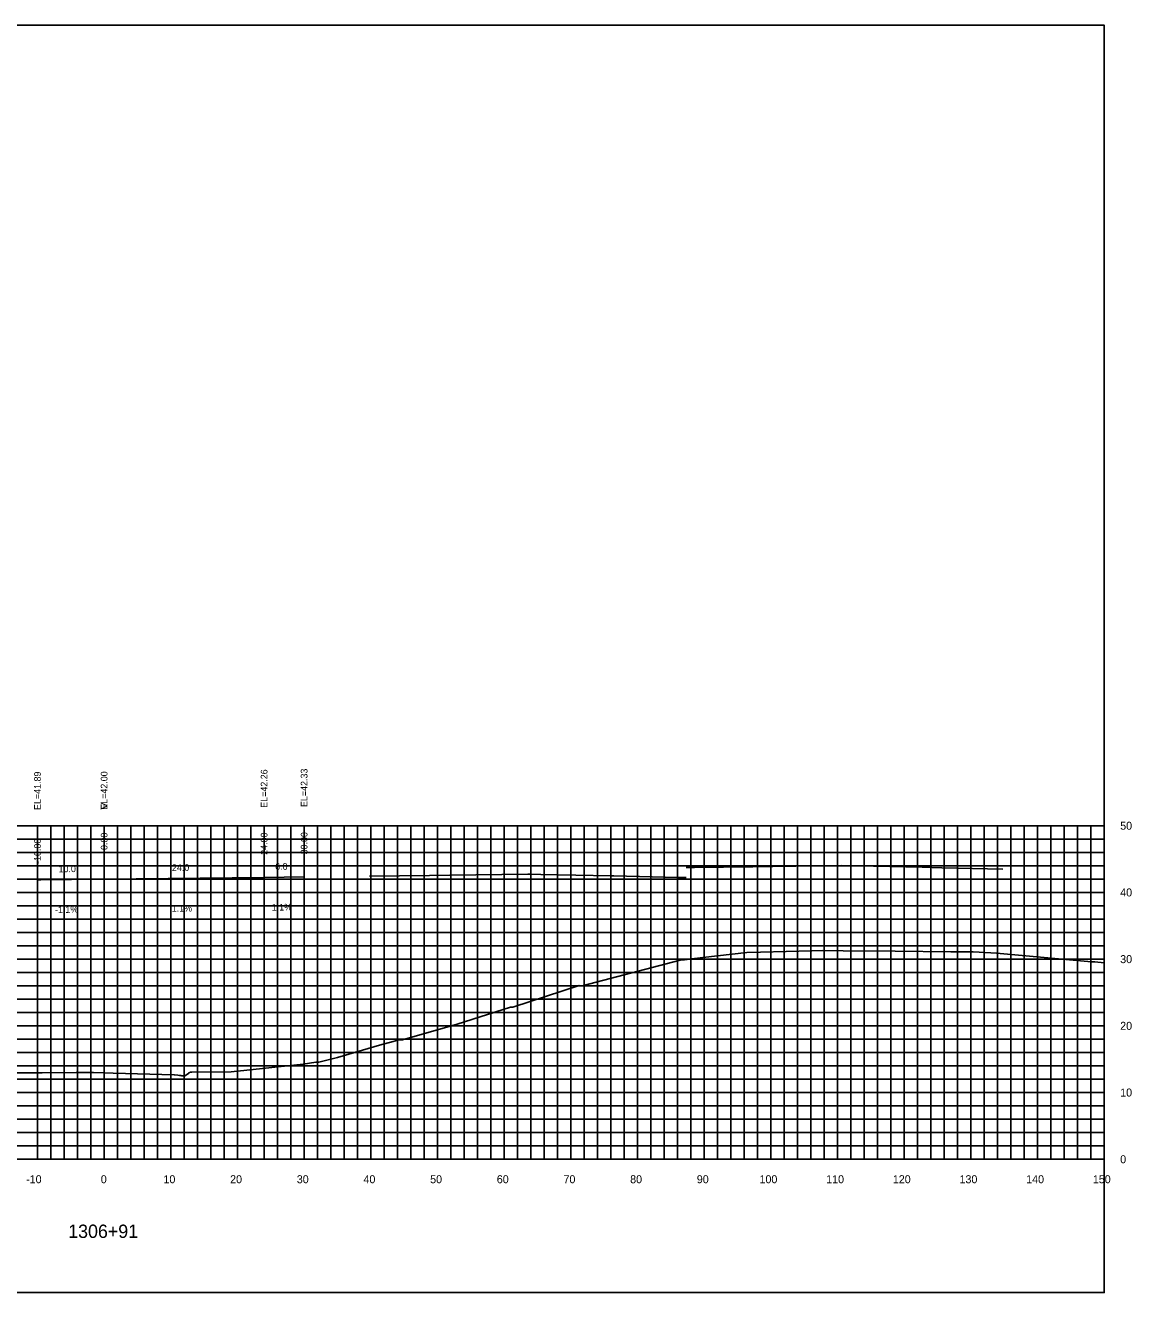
# Model space of a CAD drawing. Extents: x 1797714 to 1804825, y 249015 to 250269.
# Drawn here: x 1804632.3 to 1804798.3, y 249628.2 to 249818.2 of the extents above; entities that cross this region are included whole.
import ezdxf

# ---------------------------------------------------------------- set-up
doc = ezdxf.new("R2010")
doc.units = 0
for name, color, linetype in [('1', 7, 'Continuous'), ('10', 7, 'Continuous'), ('3', 7, 'Continuous'), ('31', 7, 'Continuous'), ('4', 7, 'Continuous'), ('60', 7, 'Continuous'), ('CL-CNST', 7, 'Continuous'), ('Level 62', 7, 'Continuous'), ('M-ROADS', 7, 'Continuous'), ('WEARING', 7, 'Continuous')]:
    doc.layers.add(name, color=color, linetype=linetype)

msp = doc.modelspace()

# ---------------------------------------------------------------- linework, layer by layer
for p, q in [((1804668.16, 249690.43), (1804668.16, 249692.43)), ((1804668.16, 249690.43), (1804668.16, 249692.43)), ((1804674.16, 249690.5), (1804674.16, 249692.5)), ((1804634.16, 249690.06), (1804634.16, 249692.06)), ((1804644.16, 249690.17), (1804644.16, 249692.17))]:
    msp.add_line(p, q)
msp.add_lwpolyline([(1804494.16, 249628.17), (1804794.16, 249628.17), (1804794.16, 249818.17), (1804494.16, 249818.17)], close=True)
at = {"layer": '60'}
for p, q in [((1804794.16, 249648.17), (1804794.16, 249698.17)), ((1804794.22, 249698.17), (1804794.16, 249698.17)), ((1804794.22, 249688.17), (1804794.16, 249688.17)), ((1804794.22, 249678.17), (1804794.16, 249678.17)), ((1804794.22, 249668.17), (1804794.16, 249668.17)), ((1804794.22, 249658.17), (1804794.16, 249658.17)), ((1804494.16, 249648.17), (1804794.16, 249648.17)), ((1804634.16, 249648.11), (1804634.16, 249648.17)), ((1804644.16, 249648.11), (1804644.16, 249648.17)), ((1804654.16, 249648.11), (1804654.16, 249648.17)), ((1804664.16, 249648.11), (1804664.16, 249648.17)), ((1804674.16, 249648.11), (1804674.16, 249648.17)), ((1804684.16, 249648.11), (1804684.16, 249648.17)), ((1804694.16, 249648.11), (1804694.16, 249648.17)), ((1804704.16, 249648.11), (1804704.16, 249648.17)), ((1804714.16, 249648.11), (1804714.16, 249648.17)), ((1804724.16, 249648.11), (1804724.16, 249648.17)), ((1804734.16, 249648.11), (1804734.16, 249648.17)), ((1804744.16, 249648.11), (1804744.16, 249648.17)), ((1804754.16, 249648.11), (1804754.16, 249648.17)), ((1804764.16, 249648.11), (1804764.16, 249648.17)), ((1804774.16, 249648.11), (1804774.16, 249648.17)), ((1804784.16, 249648.11), (1804784.16, 249648.17)), ((1804794.16, 249648.11), (1804794.16, 249648.17)), ((1804794.22, 249648.17), (1804794.16, 249648.17))]:
    msp.add_line(p, q, dxfattribs=at)
at = {"layer": 'CL-CNST'}
for points in [[(1804634.16, 249690.06), (1804644.16, 249690.17), (1804668.16, 249690.43), (1804668.16, 249690.43), (1804674.16, 249690.5)], [(1804683.96, 249690.6), (1804692.96, 249690.72), (1804696.02, 249690.75), (1804707.73, 249690.9), (1804708.09, 249690.9), (1804709.65, 249690.87), (1804720.15, 249690.65), (1804720.59, 249690.64), (1804730.2, 249690.43), (1804730.3, 249690.43), (1804731.45, 249690.4)], [(1804634.16, 249690.07), (1804634.66, 249690.07), (1804643.92, 249690.16), (1804643.94, 249690.16)]]:
    msp.add_lwpolyline(points, dxfattribs=at)
at = {"layer": 'Level 62'}
for p, q in [((1804494.16, 249698.17), (1804794.16, 249698.17)), ((1804494.16, 249698.17), (1804794.16, 249698.17)), ((1804634.16, 249648.17), (1804634.16, 249698.17)), ((1804634.16, 249648.17), (1804634.16, 249698.17)), ((1804636.16, 249648.17), (1804636.16, 249698.17)), ((1804636.16, 249648.17), (1804636.16, 249698.17)), ((1804638.16, 249648.17), (1804638.16, 249698.17)), ((1804638.16, 249648.17), (1804638.16, 249698.17)), ((1804640.16, 249648.17), (1804640.16, 249698.17)), ((1804640.16, 249648.17), (1804640.16, 249698.17)), ((1804642.16, 249648.17), (1804642.16, 249698.17)), ((1804642.16, 249648.17), (1804642.16, 249698.17)), ((1804644.16, 249648.17), (1804644.16, 249698.17)), ((1804644.16, 249648.17), (1804644.16, 249698.17)), ((1804646.16, 249648.17), (1804646.16, 249698.17)), ((1804646.16, 249648.17), (1804646.16, 249698.17)), ((1804648.16, 249648.17), (1804648.16, 249698.17)), ((1804648.16, 249648.17), (1804648.16, 249698.17)), ((1804650.16, 249648.17), (1804650.16, 249698.17)), ((1804650.16, 249648.17), (1804650.16, 249698.17)), ((1804652.16, 249648.17), (1804652.16, 249698.17)), ((1804652.16, 249648.17), (1804652.16, 249698.17)), ((1804654.16, 249648.17), (1804654.16, 249698.17)), ((1804654.16, 249648.17), (1804654.16, 249698.17)), ((1804656.16, 249648.17), (1804656.16, 249698.17)), ((1804656.16, 249648.17), (1804656.16, 249698.17)), ((1804658.16, 249648.17), (1804658.16, 249698.17)), ((1804658.16, 249648.17), (1804658.16, 249698.17)), ((1804660.16, 249648.17), (1804660.16, 249698.17)), ((1804660.16, 249648.17), (1804660.16, 249698.17)), ((1804662.16, 249648.17), (1804662.16, 249698.17)), ((1804662.16, 249648.17), (1804662.16, 249698.17)), ((1804664.16, 249648.17), (1804664.16, 249698.17)), ((1804664.16, 249648.17), (1804664.16, 249698.17)), ((1804666.16, 249648.17), (1804666.16, 249698.17)), ((1804666.16, 249648.17), (1804666.16, 249698.17)), ((1804668.16, 249648.17), (1804668.16, 249698.17)), ((1804668.16, 249648.17), (1804668.16, 249698.17)), ((1804670.16, 249648.17), (1804670.16, 249698.17)), ((1804670.16, 249648.17), (1804670.16, 249698.17)), ((1804672.16, 249648.17), (1804672.16, 249698.17)), ((1804672.16, 249648.17), (1804672.16, 249698.17)), ((1804674.16, 249648.17), (1804674.16, 249698.17)), ((1804674.16, 249648.17), (1804674.16, 249698.17)), ((1804676.16, 249648.17), (1804676.16, 249698.17)), ((1804676.16, 249648.17), (1804676.16, 249698.17)), ((1804678.16, 249648.17), (1804678.16, 249698.17)), ((1804678.16, 249648.17), (1804678.16, 249698.17)), ((1804680.16, 249648.17), (1804680.16, 249698.17)), ((1804680.16, 249648.17), (1804680.16, 249698.17)), ((1804682.16, 249648.17), (1804682.16, 249698.17)), ((1804682.16, 249648.17), (1804682.16, 249698.17)), ((1804684.16, 249648.17), (1804684.16, 249698.17)), ((1804684.16, 249648.17), (1804684.16, 249698.17)), ((1804686.16, 249648.17), (1804686.16, 249698.17)), ((1804686.16, 249648.17), (1804686.16, 249698.17)), ((1804688.16, 249648.17), (1804688.16, 249698.17)), ((1804688.16, 249648.17), (1804688.16, 249698.17)), ((1804690.16, 249648.17), (1804690.16, 249698.17)), ((1804690.16, 249648.17), (1804690.16, 249698.17)), ((1804692.16, 249648.17), (1804692.16, 249698.17)), ((1804692.16, 249648.17), (1804692.16, 249698.17)), ((1804694.16, 249648.17), (1804694.16, 249698.17)), ((1804694.16, 249648.17), (1804694.16, 249698.17)), ((1804696.16, 249648.17), (1804696.16, 249698.17)), ((1804696.16, 249648.17), (1804696.16, 249698.17)), ((1804698.16, 249648.17), (1804698.16, 249698.17)), ((1804698.16, 249648.17), (1804698.16, 249698.17)), ((1804700.16, 249648.17), (1804700.16, 249698.17)), ((1804700.16, 249648.17), (1804700.16, 249698.17)), ((1804702.16, 249648.17), (1804702.16, 249698.17)), ((1804702.16, 249648.17), (1804702.16, 249698.17)), ((1804704.16, 249648.17), (1804704.16, 249698.17)), ((1804704.16, 249648.17), (1804704.16, 249698.17)), ((1804706.16, 249648.17), (1804706.16, 249698.17)), ((1804706.16, 249648.17), (1804706.16, 249698.17)), ((1804708.16, 249648.17), (1804708.16, 249698.17)), ((1804708.16, 249648.17), (1804708.16, 249698.17)), ((1804710.16, 249648.17), (1804710.16, 249698.17)), ((1804710.16, 249648.17), (1804710.16, 249698.17)), ((1804712.16, 249648.17), (1804712.16, 249698.17)), ((1804712.16, 249648.17), (1804712.16, 249698.17)), ((1804714.16, 249648.17), (1804714.16, 249698.17)), ((1804714.16, 249648.17), (1804714.16, 249698.17)), ((1804716.16, 249648.17), (1804716.16, 249698.17)), ((1804716.16, 249648.17), (1804716.16, 249698.17)), ((1804718.16, 249648.17), (1804718.16, 249698.17)), ((1804718.16, 249648.17), (1804718.16, 249698.17)), ((1804720.16, 249648.17), (1804720.16, 249698.17)), ((1804720.16, 249648.17), (1804720.16, 249698.17)), ((1804722.16, 249648.17), (1804722.16, 249698.17)), ((1804722.16, 249648.17), (1804722.16, 249698.17)), ((1804724.16, 249648.17), (1804724.16, 249698.17)), ((1804724.16, 249648.17), (1804724.16, 249698.17)), ((1804726.16, 249648.17), (1804726.16, 249698.17)), ((1804726.16, 249648.17), (1804726.16, 249698.17)), ((1804728.16, 249648.17), (1804728.16, 249698.17)), ((1804728.16, 249648.17), (1804728.16, 249698.17)), ((1804730.16, 249648.17), (1804730.16, 249698.17)), ((1804730.16, 249648.17), (1804730.16, 249698.17)), ((1804732.16, 249648.17), (1804732.16, 249698.17)), ((1804732.16, 249648.17), (1804732.16, 249698.17)), ((1804734.16, 249648.17), (1804734.16, 249698.17)), ((1804734.16, 249648.17), (1804734.16, 249698.17)), ((1804736.16, 249648.17), (1804736.16, 249698.17)), ((1804736.16, 249648.17), (1804736.16, 249698.17)), ((1804738.16, 249648.17), (1804738.16, 249698.17)), ((1804738.16, 249648.17), (1804738.16, 249698.17)), ((1804740.16, 249648.17), (1804740.16, 249698.17)), ((1804740.16, 249648.17), (1804740.16, 249698.17)), ((1804742.16, 249648.17), (1804742.16, 249698.17)), ((1804742.16, 249648.17), (1804742.16, 249698.17)), ((1804744.16, 249648.17), (1804744.16, 249698.17)), ((1804744.16, 249648.17), (1804744.16, 249698.17)), ((1804746.16, 249648.17), (1804746.16, 249698.17)), ((1804746.16, 249648.17), (1804746.16, 249698.17)), ((1804748.16, 249648.17), (1804748.16, 249698.17)), ((1804748.16, 249648.17), (1804748.16, 249698.17)), ((1804750.16, 249648.17), (1804750.16, 249698.17)), ((1804750.16, 249648.17), (1804750.16, 249698.17)), ((1804752.16, 249648.17), (1804752.16, 249698.17)), ((1804752.16, 249648.17), (1804752.16, 249698.17)), ((1804754.16, 249648.17), (1804754.16, 249698.17)), ((1804754.16, 249648.17), (1804754.16, 249698.17)), ((1804756.16, 249648.17), (1804756.16, 249698.17)), ((1804756.16, 249648.17), (1804756.16, 249698.17)), ((1804758.16, 249648.17), (1804758.16, 249698.17)), ((1804758.16, 249648.17), (1804758.16, 249698.17)), ((1804760.16, 249648.17), (1804760.16, 249698.17)), ((1804760.16, 249648.17), (1804760.16, 249698.17)), ((1804762.16, 249648.17), (1804762.16, 249698.17)), ((1804762.16, 249648.17), (1804762.16, 249698.17)), ((1804764.16, 249648.17), (1804764.16, 249698.17)), ((1804764.16, 249648.17), (1804764.16, 249698.17)), ((1804766.16, 249648.17), (1804766.16, 249698.17)), ((1804766.16, 249648.17), (1804766.16, 249698.17)), ((1804768.16, 249648.17), (1804768.16, 249698.17)), ((1804768.16, 249648.17), (1804768.16, 249698.17)), ((1804770.16, 249648.17), (1804770.16, 249698.17)), ((1804770.16, 249648.17), (1804770.16, 249698.17)), ((1804772.16, 249648.17), (1804772.16, 249698.17)), ((1804772.16, 249648.17), (1804772.16, 249698.17)), ((1804774.16, 249648.17), (1804774.16, 249698.17)), ((1804774.16, 249648.17), (1804774.16, 249698.17)), ((1804776.16, 249648.17), (1804776.16, 249698.17)), ((1804776.16, 249648.17), (1804776.16, 249698.17)), ((1804778.16, 249648.17), (1804778.16, 249698.17)), ((1804778.16, 249648.17), (1804778.16, 249698.17)), ((1804780.16, 249648.17), (1804780.16, 249698.17)), ((1804780.16, 249648.17), (1804780.16, 249698.17)), ((1804782.16, 249648.17), (1804782.16, 249698.17)), ((1804782.16, 249648.17), (1804782.16, 249698.17)), ((1804784.16, 249648.17), (1804784.16, 249698.17)), ((1804784.16, 249648.17), (1804784.16, 249698.17)), ((1804786.16, 249648.17), (1804786.16, 249698.17)), ((1804786.16, 249648.17), (1804786.16, 249698.17)), ((1804788.16, 249648.17), (1804788.16, 249698.17)), ((1804788.16, 249648.17), (1804788.16, 249698.17)), ((1804790.16, 249648.17), (1804790.16, 249698.17)), ((1804790.16, 249648.17), (1804790.16, 249698.17)), ((1804792.16, 249648.17), (1804792.16, 249698.17)), ((1804792.16, 249648.17), (1804792.16, 249698.17)), ((1804794.16, 249648.17), (1804794.16, 249698.17)), ((1804794.16, 249648.17), (1804794.16, 249698.17)), ((1804494.16, 249696.17), (1804794.16, 249696.17)), ((1804494.16, 249696.17), (1804794.16, 249696.17)), ((1804494.16, 249694.17), (1804794.16, 249694.17)), ((1804494.16, 249694.17), (1804794.16, 249694.17)), ((1804494.16, 249692.17), (1804794.16, 249692.17)), ((1804494.16, 249692.17), (1804794.16, 249692.17)), ((1804494.16, 249690.17), (1804794.16, 249690.17)), ((1804494.16, 249690.17), (1804794.16, 249690.17)), ((1804494.16, 249688.17), (1804794.16, 249688.17)), ((1804494.16, 249688.17), (1804794.16, 249688.17)), ((1804494.16, 249686.17), (1804794.16, 249686.17)), ((1804494.16, 249686.17), (1804794.16, 249686.17)), ((1804494.16, 249684.17), (1804794.16, 249684.17)), ((1804494.16, 249684.17), (1804794.16, 249684.17)), ((1804494.16, 249682.17), (1804794.16, 249682.17)), ((1804494.16, 249682.17), (1804794.16, 249682.17)), ((1804494.16, 249680.17), (1804794.16, 249680.17)), ((1804494.16, 249680.17), (1804794.16, 249680.17)), ((1804494.16, 249678.17), (1804794.16, 249678.17)), ((1804494.16, 249678.17), (1804794.16, 249678.17)), ((1804494.16, 249676.17), (1804794.16, 249676.17)), ((1804494.16, 249676.17), (1804794.16, 249676.17)), ((1804494.16, 249674.17), (1804794.16, 249674.17)), ((1804494.16, 249674.17), (1804794.16, 249674.17)), ((1804494.16, 249672.17), (1804794.16, 249672.17)), ((1804494.16, 249672.17), (1804794.16, 249672.17)), ((1804494.16, 249670.17), (1804794.16, 249670.17)), ((1804494.16, 249670.17), (1804794.16, 249670.17)), ((1804494.16, 249668.17), (1804794.16, 249668.17)), ((1804494.16, 249668.17), (1804794.16, 249668.17)), ((1804494.16, 249666.17), (1804794.16, 249666.17)), ((1804494.16, 249666.17), (1804794.16, 249666.17)), ((1804494.16, 249664.17), (1804794.16, 249664.17)), ((1804494.16, 249664.17), (1804794.16, 249664.17)), ((1804494.16, 249662.17), (1804794.16, 249662.17)), ((1804494.16, 249662.17), (1804794.16, 249662.17)), ((1804494.16, 249660.17), (1804794.16, 249660.17)), ((1804494.16, 249660.17), (1804794.16, 249660.17)), ((1804494.16, 249658.17), (1804794.16, 249658.17)), ((1804494.16, 249658.17), (1804794.16, 249658.17)), ((1804494.16, 249656.17), (1804794.16, 249656.17)), ((1804494.16, 249656.17), (1804794.16, 249656.17)), ((1804494.16, 249654.17), (1804794.16, 249654.17)), ((1804494.16, 249654.17), (1804794.16, 249654.17)), ((1804494.16, 249652.17), (1804794.16, 249652.17)), ((1804494.16, 249652.17), (1804794.16, 249652.17)), ((1804494.16, 249650.17), (1804794.16, 249650.17)), ((1804494.16, 249650.17), (1804794.16, 249650.17)), ((1804494.16, 249648.17), (1804794.16, 249648.17)), ((1804494.16, 249648.17), (1804794.16, 249648.17))]:
    msp.add_line(p, q, dxfattribs=at)
at = {"layer": 'M-ROADS'}
msp.add_lwpolyline([(1804630.31, 249661.13), (1804632.86, 249661.13), (1804634.38, 249661.13), (1804634.87, 249661.13), (1804639.96, 249661.15), (1804641.58, 249661.16), (1804641.7, 249661.16), (1804642.56, 249661.17), (1804645.51, 249661.09), (1804654.68, 249660.84), (1804654.73, 249660.83), (1804655.21, 249660.77), (1804655.46, 249660.74), (1804655.61, 249660.72), (1804655.71, 249660.7), (1804655.79, 249660.69), (1804655.84, 249660.69), (1804655.89, 249660.68), (1804655.92, 249660.68), (1804655.95, 249660.67), (1804655.98, 249660.67), (1804656, 249660.67), (1804656.02, 249660.66), (1804656.03, 249660.66), (1804656.04, 249660.66), (1804656.06, 249660.66), (1804656.07, 249660.66), (1804656.08, 249660.65), (1804656.09, 249660.65), (1804656.09, 249660.65), (1804656.1, 249660.65), (1804656.24, 249660.63), (1804656.85, 249661.07), (1804656.88, 249661.1), (1804657.11, 249661.21), (1804657.3, 249661.21), (1804663.2, 249661.26), (1804674, 249662.4), (1804675.91, 249662.71), (1804676.35, 249662.72), (1804679.17, 249663.42), (1804685.45, 249665.25), (1804686.74, 249665.6), (1804686.96, 249665.66), (1804688.4, 249666.07), (1804688.88, 249666.07), (1804688.91, 249666.07), (1804697.1, 249668.42), (1804705.09, 249670.96), (1804705.48, 249670.99), (1804715.43, 249674.2), (1804715.7, 249674.19), (1804715.87, 249674.19), (1804730.57, 249678.03), (1804731.21, 249678.07), (1804731.42, 249678.11), (1804731.44, 249678.11), (1804731.47, 249678.11), (1804731.51, 249678.12), (1804731.6, 249678.13), (1804731.92, 249678.16), (1804733.95, 249678.39), (1804740.55, 249679.17), (1804742.61, 249679.22), (1804750.3, 249679.41), (1804751.85, 249679.45), (1804755.01, 249679.42), (1804762.81, 249679.36), (1804771.15, 249679.27), (1804774.52, 249679.24), (1804777.16, 249679.12), (1804778.03, 249679.08), (1804779.68, 249678.93), (1804792.26, 249677.78), (1804792.51, 249677.78), (1804792.77, 249677.78), (1804794.16, 249677.59)], dxfattribs=at)
at = {"layer": 'WEARING'}
msp.add_lwpolyline([(1804731.45, 249691.92), (1804732.59, 249691.93), (1804732.71, 249691.93), (1804741.48, 249692.03), (1804742.76, 249692.06), (1804744.45, 249692.08), (1804754.82, 249692.21), (1804757.12, 249692.16), (1804766.88, 249691.94), (1804769.8, 249691.87), (1804778.94, 249691.67)], dxfattribs=at)

# ---------------------------------------------------------------- texts
at = {"layer": '1'}
msp.add_text('1306+91', height=2, dxfattribs=at).set_placement((1804638.77, 249636.37))
at = {"layer": '10'}
for s, p in [('-10', (1804632.46, 249644.57)), ('0', (1804643.66, 249644.57)), ('10', (1804653.06, 249644.57)), ('20', (1804663.06, 249644.57)), ('30', (1804673.06, 249644.57)), ('40', (1804683.06, 249644.57)), ('50', (1804693.06, 249644.57)), ('60', (1804703.06, 249644.57)), ('70', (1804713.06, 249644.57)), ('80', (1804723.06, 249644.57)), ('90', (1804733.06, 249644.57)), ('100', (1804742.46, 249644.57)), ('110', (1804752.46, 249644.57)), ('120', (1804762.46, 249644.57)), ('130', (1804772.46, 249644.57)), ('140', (1804782.46, 249644.57)), ('150', (1804792.46, 249644.57))]:
    msp.add_text(s, height=1.2, dxfattribs=at).set_placement(p)
at = {"layer": '3'}
for s, p in [('EL=41.89', (1804634.66, 249700.53)), ('EL=42.00', (1804644.66, 249700.56)), ('EL=42.26', (1804668.66, 249700.86)), ('EL=42.26', (1804668.66, 249700.86)), ('EL=42.33', (1804674.66, 249700.97)), ('-10.00', (1804634.66, 249692.44)), ('0.00', (1804644.66, 249694.53)), ('24.00', (1804668.66, 249693.8)), ('24.00', (1804668.66, 249693.8)), ('30.00', (1804674.66, 249693.87))]:
    msp.add_text(s, height=1, rotation=90, dxfattribs=at).set_placement(p)
at = {"layer": '31'}
for s, p in [('50', (1804796.56, 249697.57)), ('40', (1804796.56, 249687.57)), ('30', (1804796.56, 249677.57)), ('20', (1804796.56, 249667.57)), ('10', (1804796.56, 249657.57)), ('0', (1804796.56, 249647.57))]:
    msp.add_text(s, height=1.2, dxfattribs=at).set_placement(p)
at = {"layer": '4'}
for s, p in [('24.0', (1804654.33, 249691.38)), ('6.0', (1804669.82, 249691.55)), ('10.0', (1804637.33, 249691.19)), ('-1.1%', (1804636.8, 249685.09)), ('1.1%', (1804654.3, 249685.28)), ('1.1%', (1804669.3, 249685.44))]:
    msp.add_text(s, height=1, rotation=0.6302, dxfattribs=at).set_placement(p)
at = {"layer": '60'}
msp.add_text('>', height=1.5, dxfattribs=at).set_placement((1804643.55, 249700.42))

doc.saveas('drawing.dxf')
